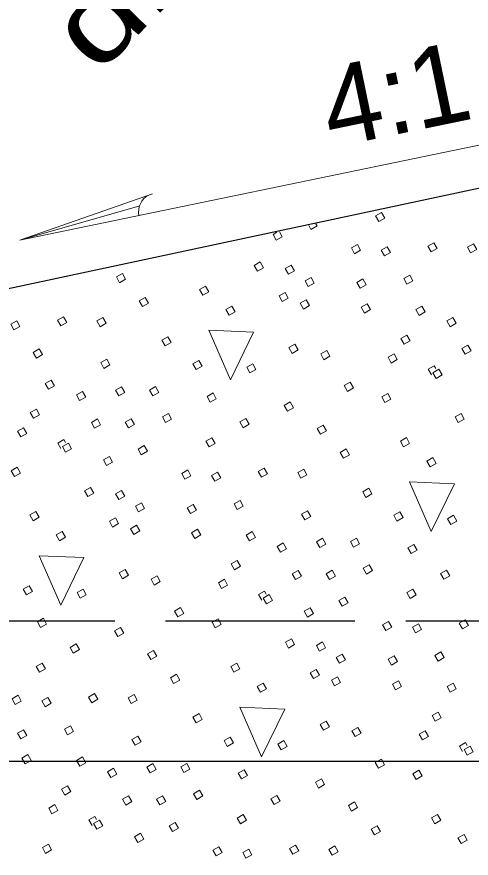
# Model space of a CAD drawing. Extents: x 1083.1 to 1117.1, y 697.4 to 741.4.
# Drawn here: x 1100.178 to 1101.072, y 729.816 to 731.469 of the extents above; entities that cross this region are included whole.
import ezdxf
from ezdxf.enums import TextEntityAlignment as Align

# ---------------------------------------------------------------- set-up
doc = ezdxf.new("R2010")
doc.units = 0
doc.header["$LTSCALE"] = 0.062
doc.linetypes.add('LONG_DASHED', pattern=[7.5, 6, -1.5])
doc.layers.add('1', color=7, linetype='Continuous', lineweight=13)

msp = doc.modelspace()

# ---------------------------------------------------------------- linework, layer by layer
at = {"layer": '1'}
for p, q in [((1101.18625, 731.23717), (1100.18442, 731.03)), ((1100.44525, 731.12058), (1100.18442, 731.03)), ((1100.42017, 731.09708), (1100.18442, 731.03)), ((1100.68217, 731.04108), (1100.68958, 731.04525)), ((1100.99358, 730.76558), (1100.98742, 730.77642)), ((1100.26508, 730.62042), (1100.25892, 730.63125)), ((1100.65992, 730.32283), (1100.65383, 730.33367)), ((1101.05483, 730.02525), (1101.04875, 730.03617)), ((1100.32633, 729.88017), (1100.32025, 729.891))]:
    msp.add_line(p, q, dxfattribs=at)
at = {"layer": '1', "lineweight": 25}
for p, q in [((1101.38492, 731.19542), (1100.024, 730.90508)), ((1096.99167, 730.00642), (1101.94625, 730.00642))]:
    msp.add_line(p, q, dxfattribs=at)
at = {"layer": '1', "linetype": 'LONG_DASHED', "lineweight": 25}
msp.add_line((1099.999, 730.28225), (1101.37692, 730.28225), dxfattribs=at)
at = {"layer": '1'}
for points in [[(1100.88383, 731.07775), (1100.89567, 731.0845), (1100.902, 731.07325), (1100.89017, 731.0665)], [(1100.83617, 731.0145), (1100.848, 731.02125), (1100.85433, 731.01), (1100.8425, 731.00325)], [(1100.98683, 731.01792), (1100.99867, 731.02458), (1101.005, 731.01342), (1100.99317, 731.00667)], [(1101.06433, 731.01617), (1101.07625, 731.02292), (1101.08258, 731.01167), (1101.07067, 731.00492)], [(1100.89492, 731.01008), (1100.90675, 731.01683), (1100.91308, 731.00558), (1100.90125, 730.99883)], [(1100.64517, 730.98025), (1100.657, 730.987), (1100.66342, 730.97575), (1100.6515, 730.969)], [(1100.70617, 730.97417), (1100.718, 730.98092), (1100.72433, 730.96967), (1100.7125, 730.96292)], [(1100.37425, 730.9575), (1100.38608, 730.96425), (1100.39242, 730.953), (1100.38058, 730.94625)], [(1100.74508, 730.95017), (1100.757, 730.95683), (1100.76333, 730.94558), (1100.7515, 730.93892)], [(1100.84725, 730.94683), (1100.85908, 730.95358), (1100.86542, 730.94233), (1100.85358, 730.93558)], [(1100.93917, 730.95467), (1100.951, 730.96133), (1100.95733, 730.95008), (1100.9455, 730.94342)], [(1100.53767, 730.93275), (1100.5495, 730.9395), (1100.55583, 730.92825), (1100.544, 730.9215)], [(1100.694, 730.92033), (1100.70583, 730.92708), (1100.71217, 730.91583), (1100.70033, 730.90908)], [(1100.41917, 730.91058), (1100.431, 730.91733), (1100.43733, 730.90608), (1100.4255, 730.89942)], [(1100.73575, 730.90583), (1100.74758, 730.9125), (1100.75392, 730.90133), (1100.74208, 730.89458)], [(1100.85567, 730.89792), (1100.8675, 730.90467), (1100.87383, 730.89342), (1100.862, 730.88667)], [(1100.58967, 730.89358), (1100.6015, 730.90025), (1100.60783, 730.889), (1100.596, 730.88233)], [(1100.96292, 730.89333), (1100.97475, 730.90008), (1100.98108, 730.88883), (1100.96925, 730.88208)], [(1100.16642, 730.865), (1100.17825, 730.87167), (1100.18458, 730.86042), (1100.17275, 730.85375)], [(1100.25833, 730.87275), (1100.27017, 730.8795), (1100.2765, 730.86825), (1100.26467, 730.8615)], [(1100.33592, 730.87108), (1100.34775, 730.87783), (1100.35408, 730.86658), (1100.34225, 730.85983)], [(1101.02417, 730.87108), (1101.036, 730.87783), (1101.04233, 730.86658), (1101.0305, 730.85983)], [(1100.46358, 730.83333), (1100.47542, 730.84008), (1100.48175, 730.82883), (1100.46992, 730.82208)], [(1100.55592, 730.85275), (1100.59842, 730.75533), (1100.644, 730.849)], [(1100.9335, 730.83658), (1100.94533, 730.84325), (1100.95167, 730.83208), (1100.93983, 730.82533)], [(1100.7135, 730.81875), (1100.72533, 730.8255), (1100.73167, 730.81425), (1100.71983, 730.8075)], [(1101.05358, 730.817), (1101.06542, 730.82375), (1101.07175, 730.8125), (1101.05992, 730.80575)], [(1100.21067, 730.8095), (1100.2225, 730.81625), (1100.22883, 730.805), (1100.217, 730.79825)], [(1100.776, 730.80633), (1100.78783, 730.81308), (1100.79417, 730.80183), (1100.78233, 730.79508)], [(1100.90833, 730.79975), (1100.92017, 730.80642), (1100.9265, 730.79517), (1100.91467, 730.7885)], [(1100.34333, 730.78925), (1100.35517, 730.79592), (1100.3615, 730.78467), (1100.34967, 730.778)], [(1100.52467, 730.787), (1100.5365, 730.79375), (1100.54283, 730.7825), (1100.531, 730.77575)], [(1100.6305, 730.78025), (1100.64233, 730.787), (1100.64867, 730.77575), (1100.63683, 730.769)], [(1100.99658, 730.7695), (1101.00842, 730.77625), (1101.01475, 730.765), (1101.00292, 730.75833)], [(1100.23442, 730.74825), (1100.24625, 730.75492), (1100.25258, 730.74367), (1100.24075, 730.737)], [(1100.37275, 730.73517), (1100.38458, 730.74183), (1100.39092, 730.73058), (1100.37908, 730.72392)], [(1100.43942, 730.7355), (1100.45125, 730.74217), (1100.45758, 730.73092), (1100.44575, 730.72425)], [(1100.82208, 730.74408), (1100.83392, 730.75075), (1100.84025, 730.7395), (1100.82842, 730.73283)], [(1100.29567, 730.72592), (1100.3075, 730.73267), (1100.31383, 730.72142), (1100.302, 730.71475)], [(1100.55242, 730.723), (1100.56425, 730.72975), (1100.57058, 730.7185), (1100.55875, 730.71183)], [(1100.89592, 730.72208), (1100.90775, 730.72883), (1100.91408, 730.71758), (1100.90225, 730.71083)], [(1100.70417, 730.70525), (1100.716, 730.712), (1100.72233, 730.70075), (1100.7105, 730.694)], [(1100.205, 730.69142), (1100.21683, 730.69817), (1100.22317, 730.68692), (1100.21133, 730.68017)], [(1100.46458, 730.68283), (1100.47642, 730.68958), (1100.48275, 730.67833), (1100.47092, 730.67158)], [(1101.04008, 730.68275), (1101.05192, 730.68942), (1101.05825, 730.67817), (1101.04642, 730.6715)], [(1100.32508, 730.67183), (1100.33692, 730.67858), (1100.34325, 730.66733), (1100.33142, 730.66067)], [(1100.39175, 730.67217), (1100.40358, 730.67892), (1100.40992, 730.66767), (1100.39808, 730.661)], [(1100.61683, 730.67275), (1100.62867, 730.67942), (1100.635, 730.66825), (1100.62317, 730.6615)], [(1100.17983, 730.65458), (1100.19167, 730.66133), (1100.198, 730.65008), (1100.18617, 730.64333)], [(1100.76908, 730.65992), (1100.781, 730.66667), (1100.78733, 730.65542), (1100.77542, 730.64875)], [(1100.55025, 730.63508), (1100.56208, 730.64175), (1100.56842, 730.63058), (1100.55658, 730.62383)], [(1100.9325, 730.63517), (1100.94433, 730.64192), (1100.95067, 730.63067), (1100.93883, 730.62392)], [(1100.26808, 730.62442), (1100.27992, 730.63117), (1100.28625, 730.61992), (1100.27442, 730.61317)], [(1100.41692, 730.61958), (1100.42875, 730.62633), (1100.43508, 730.61508), (1100.42325, 730.60833)], [(1100.81408, 730.61308), (1100.82592, 730.61975), (1100.83225, 730.6085), (1100.82042, 730.60183)], [(1100.34858, 730.59842), (1100.36042, 730.60508), (1100.36675, 730.59383), (1100.35492, 730.58717)], [(1100.9845, 730.596), (1100.99642, 730.60267), (1101.00275, 730.59142), (1100.99083, 730.58475)], [(1100.16742, 730.577), (1100.17925, 730.58367), (1100.18558, 730.57242), (1100.17375, 730.56575)], [(1100.50258, 730.57183), (1100.51442, 730.5785), (1100.52075, 730.56725), (1100.50892, 730.56058)], [(1100.56133, 730.56742), (1100.57317, 730.57408), (1100.5795, 730.56283), (1100.56767, 730.55617)], [(1100.65325, 730.57517), (1100.66508, 730.58192), (1100.67142, 730.57067), (1100.65958, 730.564)], [(1100.73075, 730.5735), (1100.74258, 730.58025), (1100.74892, 730.569), (1100.73708, 730.56225)], [(1100.31158, 730.53758), (1100.32342, 730.54433), (1100.32975, 730.53308), (1100.31792, 730.52633)], [(1100.8585, 730.53575), (1100.87033, 730.5425), (1100.87667, 730.53125), (1100.86483, 730.5245)], [(1100.95075, 730.55517), (1100.99333, 730.45775), (1101.03892, 730.5515)], [(1100.37258, 730.5315), (1100.38442, 730.53817), (1100.39075, 730.52692), (1100.37892, 730.52025)], [(1100.4115, 730.50742), (1100.42333, 730.51417), (1100.42967, 730.50292), (1100.41783, 730.49617)], [(1100.51367, 730.50417), (1100.5255, 730.51083), (1100.53183, 730.49958), (1100.52, 730.49292)], [(1100.60558, 730.51192), (1100.61742, 730.51867), (1100.62375, 730.50742), (1100.61192, 730.50067)], [(1100.204, 730.49008), (1100.21583, 730.49675), (1100.22225, 730.4855), (1100.21033, 730.47883)], [(1100.73825, 730.49167), (1100.75008, 730.49833), (1100.75642, 730.48708), (1100.74458, 730.48042)], [(1100.91958, 730.48942), (1100.93142, 730.49617), (1100.93775, 730.48492), (1100.92592, 730.47817)], [(1100.36042, 730.47767), (1100.37225, 730.48433), (1100.37858, 730.47317), (1100.36675, 730.46642)], [(1101.02533, 730.48267), (1101.03725, 730.48942), (1101.04358, 730.47817), (1101.03167, 730.4715)], [(1100.256, 730.45083), (1100.26792, 730.45758), (1100.27425, 730.44633), (1100.26242, 730.43958)], [(1100.40208, 730.46308), (1100.41392, 730.46983), (1100.42033, 730.45858), (1100.40842, 730.45192)], [(1100.52208, 730.45525), (1100.53392, 730.462), (1100.54025, 730.45075), (1100.52842, 730.444)], [(1100.62933, 730.45067), (1100.64117, 730.45733), (1100.6475, 730.44608), (1100.63567, 730.43942)], [(1100.76767, 730.43758), (1100.7795, 730.44425), (1100.78583, 730.433), (1100.774, 730.42633)], [(1100.83433, 730.43792), (1100.84617, 730.44458), (1100.8525, 730.43333), (1100.84067, 730.42667)], [(1100.69058, 730.42842), (1100.70242, 730.43508), (1100.70875, 730.42383), (1100.69692, 730.41717)], [(1100.94733, 730.4255), (1100.95917, 730.43217), (1100.9655, 730.42092), (1100.95367, 730.41425)], [(1100.22225, 730.41008), (1100.26483, 730.31258), (1100.31042, 730.40633)], [(1100.59992, 730.39383), (1100.61175, 730.40058), (1100.61808, 730.38933), (1100.60625, 730.38258)], [(1100.85942, 730.38525), (1100.87125, 730.392), (1100.87767, 730.38075), (1100.86575, 730.374)], [(1100.37992, 730.37608), (1100.39175, 730.38283), (1100.39808, 730.37158), (1100.38625, 730.36483)], [(1100.72, 730.37433), (1100.73183, 730.381), (1100.73817, 730.36975), (1100.72633, 730.36308)], [(1100.78667, 730.37467), (1100.7985, 730.38133), (1100.80483, 730.37008), (1100.793, 730.36342)], [(1101.01167, 730.37517), (1101.0235, 730.38192), (1101.02992, 730.37067), (1101.018, 730.36392)], [(1100.44233, 730.36367), (1100.45425, 730.37033), (1100.46058, 730.35908), (1100.44875, 730.35242)], [(1100.57475, 730.357), (1100.58658, 730.36375), (1100.59292, 730.3525), (1100.58108, 730.34575)], [(1100.19108, 730.34433), (1100.20292, 730.351), (1100.20925, 730.33975), (1100.19742, 730.33308)], [(1100.29683, 730.33758), (1100.30875, 730.34433), (1100.31508, 730.33308), (1100.30325, 730.32633)], [(1100.94517, 730.3375), (1100.957, 730.34425), (1100.96333, 730.333), (1100.9515, 730.32625)], [(1100.66292, 730.32683), (1100.67483, 730.33358), (1100.68117, 730.32233), (1100.66925, 730.31558)], [(1100.81175, 730.322), (1100.82358, 730.32875), (1100.82992, 730.3175), (1100.81808, 730.31075)], [(1100.4885, 730.30133), (1100.50033, 730.30808), (1100.50667, 730.29683), (1100.49483, 730.29008)], [(1100.74342, 730.30083), (1100.75525, 730.3075), (1100.76167, 730.29625), (1100.74975, 730.28958)], [(1100.21883, 730.28033), (1100.23067, 730.28708), (1100.237, 730.27583), (1100.22517, 730.26908)], [(1100.56233, 730.27942), (1100.57417, 730.28608), (1100.5805, 730.27483), (1100.56867, 730.26817)], [(1100.8975, 730.27425), (1100.90933, 730.28092), (1100.91567, 730.26975), (1100.90383, 730.263)], [(1100.95617, 730.26983), (1100.968, 730.2765), (1100.97442, 730.26533), (1100.9625, 730.25858)], [(1101.04808, 730.27767), (1101.06, 730.28433), (1101.06625, 730.27308), (1101.05442, 730.26642)], [(1100.37058, 730.2625), (1100.38242, 730.26925), (1100.38875, 730.258), (1100.37692, 730.25133)], [(1100.7065, 730.24), (1100.71833, 730.24675), (1100.72467, 730.2355), (1100.71283, 730.22875)], [(1100.28317, 730.23), (1100.295, 730.23675), (1100.30142, 730.2255), (1100.2895, 730.21883)], [(1100.7675, 730.23392), (1100.77933, 730.24058), (1100.78567, 730.22933), (1100.77383, 730.22267)], [(1100.4355, 730.21725), (1100.44733, 730.224), (1100.45367, 730.21275), (1100.44183, 730.206)], [(1100.80642, 730.20983), (1100.81825, 730.21658), (1100.82458, 730.20533), (1100.81275, 730.19867)], [(1100.9085, 730.20658), (1100.92033, 730.21325), (1100.92667, 730.202), (1100.91483, 730.19533)], [(1101.00042, 730.21433), (1101.01225, 730.22108), (1101.01858, 730.20983), (1101.00675, 730.20317)], [(1100.21667, 730.19233), (1100.2285, 730.19908), (1100.23483, 730.18783), (1100.223, 730.18108)], [(1100.59892, 730.1925), (1100.61075, 730.19917), (1100.61708, 730.18792), (1100.60525, 730.18125)], [(1100.4805, 730.17033), (1100.49233, 730.17708), (1100.49867, 730.16583), (1100.48683, 730.15908)], [(1100.75533, 730.18008), (1100.76717, 730.18683), (1100.7735, 730.17558), (1100.76167, 730.16883)], [(1100.65092, 730.15325), (1100.66275, 730.16), (1100.66908, 730.14875), (1100.65725, 730.142)], [(1100.797, 730.16558), (1100.80883, 730.17225), (1100.81517, 730.161), (1100.80333, 730.15433)], [(1100.91692, 730.15767), (1100.92875, 730.16442), (1100.93508, 730.15317), (1100.92325, 730.14642)], [(1101.02425, 730.15308), (1101.03608, 730.15975), (1101.04242, 730.14858), (1101.03058, 730.14183)], [(1100.169, 730.12908), (1100.18083, 730.13583), (1100.18717, 730.12458), (1100.17533, 730.11783)], [(1100.22767, 730.12467), (1100.23958, 730.13142), (1100.24592, 730.12017), (1100.234, 730.11342)], [(1100.31958, 730.1325), (1100.3315, 730.13925), (1100.33783, 730.128), (1100.32592, 730.12125)], [(1100.39717, 730.13083), (1100.409, 730.1375), (1100.41533, 730.12625), (1100.4035, 730.11958)], [(1100.61717, 730.1125), (1100.65975, 730.015), (1100.70533, 730.10875)], [(1100.52483, 730.09308), (1100.53675, 730.09983), (1100.54308, 730.08858), (1100.53117, 730.08183)], [(1100.99475, 730.09633), (1101.00667, 730.103), (1101.013, 730.09175), (1101.00108, 730.08508)], [(1100.77483, 730.0785), (1100.78667, 730.08525), (1100.793, 730.074), (1100.78117, 730.06725)], [(1100.18, 730.06142), (1100.19183, 730.06817), (1100.19825, 730.05692), (1100.18633, 730.05017)], [(1100.27192, 730.06925), (1100.28375, 730.076), (1100.29017, 730.06475), (1100.27825, 730.058)], [(1100.83725, 730.06608), (1100.84908, 730.07275), (1100.85542, 730.0615), (1100.84358, 730.05483)], [(1100.96967, 730.05942), (1100.9815, 730.06617), (1100.98783, 730.05492), (1100.976, 730.04817)], [(1100.40467, 730.04892), (1100.4165, 730.05567), (1100.42283, 730.04442), (1100.411, 730.03767)], [(1100.586, 730.04675), (1100.59783, 730.05342), (1100.60417, 730.04217), (1100.59233, 730.0355)], [(1100.69175, 730.04), (1100.70358, 730.04675), (1100.70992, 730.0355), (1100.69808, 730.02875)], [(1101.05783, 730.02925), (1101.06967, 730.036), (1101.076, 730.02475), (1101.06417, 730.018)], [(1100.18842, 730.0125), (1100.20025, 730.01925), (1100.20667, 730.008), (1100.19475, 730.00133)], [(1100.29575, 730.00792), (1100.30758, 730.01467), (1100.31392, 730.00342), (1100.30208, 729.99667)], [(1100.43408, 729.99483), (1100.44592, 730.00158), (1100.45225, 729.99033), (1100.44042, 729.98358)], [(1100.50075, 729.99517), (1100.51258, 730.00192), (1100.51892, 729.99067), (1100.50708, 729.98392)], [(1100.88333, 730.00375), (1100.89525, 730.0105), (1100.90158, 729.99925), (1100.88967, 729.9925)], [(1100.35692, 729.98567), (1100.36883, 729.99242), (1100.37517, 729.98117), (1100.36333, 729.97442)], [(1100.61367, 729.98275), (1100.6255, 729.9895), (1100.63192, 729.97825), (1100.62, 729.9715)], [(1100.95725, 729.98183), (1100.96908, 729.9885), (1100.97542, 729.97733), (1100.96358, 729.97058)], [(1100.7655, 729.965), (1100.77733, 729.97167), (1100.78367, 729.96042), (1100.77183, 729.95375)], [(1100.26633, 729.95117), (1100.27817, 729.95792), (1100.2845, 729.94667), (1100.27267, 729.93992)], [(1100.52583, 729.94258), (1100.53767, 729.94933), (1100.544, 729.93808), (1100.53217, 729.93133)], [(1100.38642, 729.93158), (1100.39825, 729.93833), (1100.40458, 729.92708), (1100.39275, 729.92033)], [(1100.45308, 729.93192), (1100.46492, 729.93867), (1100.47125, 729.92742), (1100.45942, 729.92067)], [(1100.67808, 729.93242), (1100.68992, 729.93917), (1100.69625, 729.92792), (1100.68442, 729.92125)], [(1100.24117, 729.91433), (1100.253, 729.92108), (1100.25933, 729.90983), (1100.2475, 729.90308)], [(1100.83042, 729.91967), (1100.84225, 729.92642), (1100.84858, 729.91517), (1100.83675, 729.90842)], [(1100.61158, 729.89475), (1100.62342, 729.9015), (1100.62975, 729.89025), (1100.61792, 729.88358)], [(1100.99383, 729.89492), (1101.00567, 729.90158), (1101.012, 729.89033), (1101.00017, 729.88367)], [(1100.32933, 729.88417), (1100.34117, 729.89083), (1100.3475, 729.87958), (1100.33567, 729.87292)], [(1100.47817, 729.87933), (1100.49, 729.886), (1100.49633, 729.87475), (1100.4845, 729.86808)], [(1100.87533, 729.87275), (1100.88725, 729.8795), (1100.89358, 729.86825), (1100.88167, 729.8615)], [(1100.40983, 729.85808), (1100.42167, 729.86483), (1100.428, 729.85358), (1100.41617, 729.84683)], [(1101.04583, 729.85567), (1101.05767, 729.86242), (1101.064, 729.85117), (1101.05217, 729.84442)], [(1100.22875, 729.83667), (1100.24058, 729.84342), (1100.24692, 729.83217), (1100.23508, 729.82542)], [(1100.56383, 729.8315), (1100.57575, 729.83825), (1100.58208, 729.827), (1100.57025, 729.82025)], [(1100.62258, 729.82708), (1100.63442, 729.83383), (1100.64075, 729.82258), (1100.62892, 729.81592)], [(1100.7145, 729.83492), (1100.72633, 729.84167), (1100.73267, 729.83042), (1100.72083, 729.82367)], [(1100.79208, 729.83325), (1100.80392, 729.83992), (1100.81025, 729.82867), (1100.79842, 729.822)]]:
    msp.add_lwpolyline(points, close=True, dxfattribs=at)
for points in [[(1100.76633, 731.06183), (1100.76867, 731.05775), (1100.75683, 731.05108), (1100.75242, 731.05883)], [(1100.69475, 731.04642), (1100.70033, 731.03658), (1100.6885, 731.02983), (1100.68217, 731.04108)], [(1100.98742, 730.77642), (1100.99925, 730.78317), (1101.0025, 730.7775)], [(1100.25892, 730.63125), (1100.27075, 730.638), (1100.274, 730.63233)], [(1100.65383, 730.33367), (1100.66567, 730.34042), (1100.66892, 730.33475)], [(1101.04875, 730.03617), (1101.06058, 730.04283), (1101.06383, 730.03717)], [(1100.32025, 729.891), (1100.33208, 729.89775), (1100.33533, 729.89208)]]:
    msp.add_lwpolyline(points, dxfattribs=at)
msp.add_ellipse((1100.45169, 731.08527), major_axis=(0, -0.03598), ratio=0.944544, start_param=3.5879271, end_param=4.9053032, dxfattribs=at)

# ---------------------------------------------------------------- texts
at = {"layer": '1', "width": 1.35}
msp.add_text('dia. max.', height=0.156, rotation=45.34, dxfattribs=at).set_placement((1100.73846, 731.7583), align=Align.CENTER)
at = {"layer": '1'}
msp.add_text('4:1', height=0.156, rotation=11.685, dxfattribs=at).set_placement((1100.79625, 731.21083))

doc.saveas('drawing.dxf')
